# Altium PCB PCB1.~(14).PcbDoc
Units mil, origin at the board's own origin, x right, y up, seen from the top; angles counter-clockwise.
Board outline 2228.35 x 2228.35 mil, 2 copper layers (Top Layer, Bottom Layer); 36 components, 12 nets, 120 pads, 0 vias.
Unrouted connection lines stored in the file: 3.
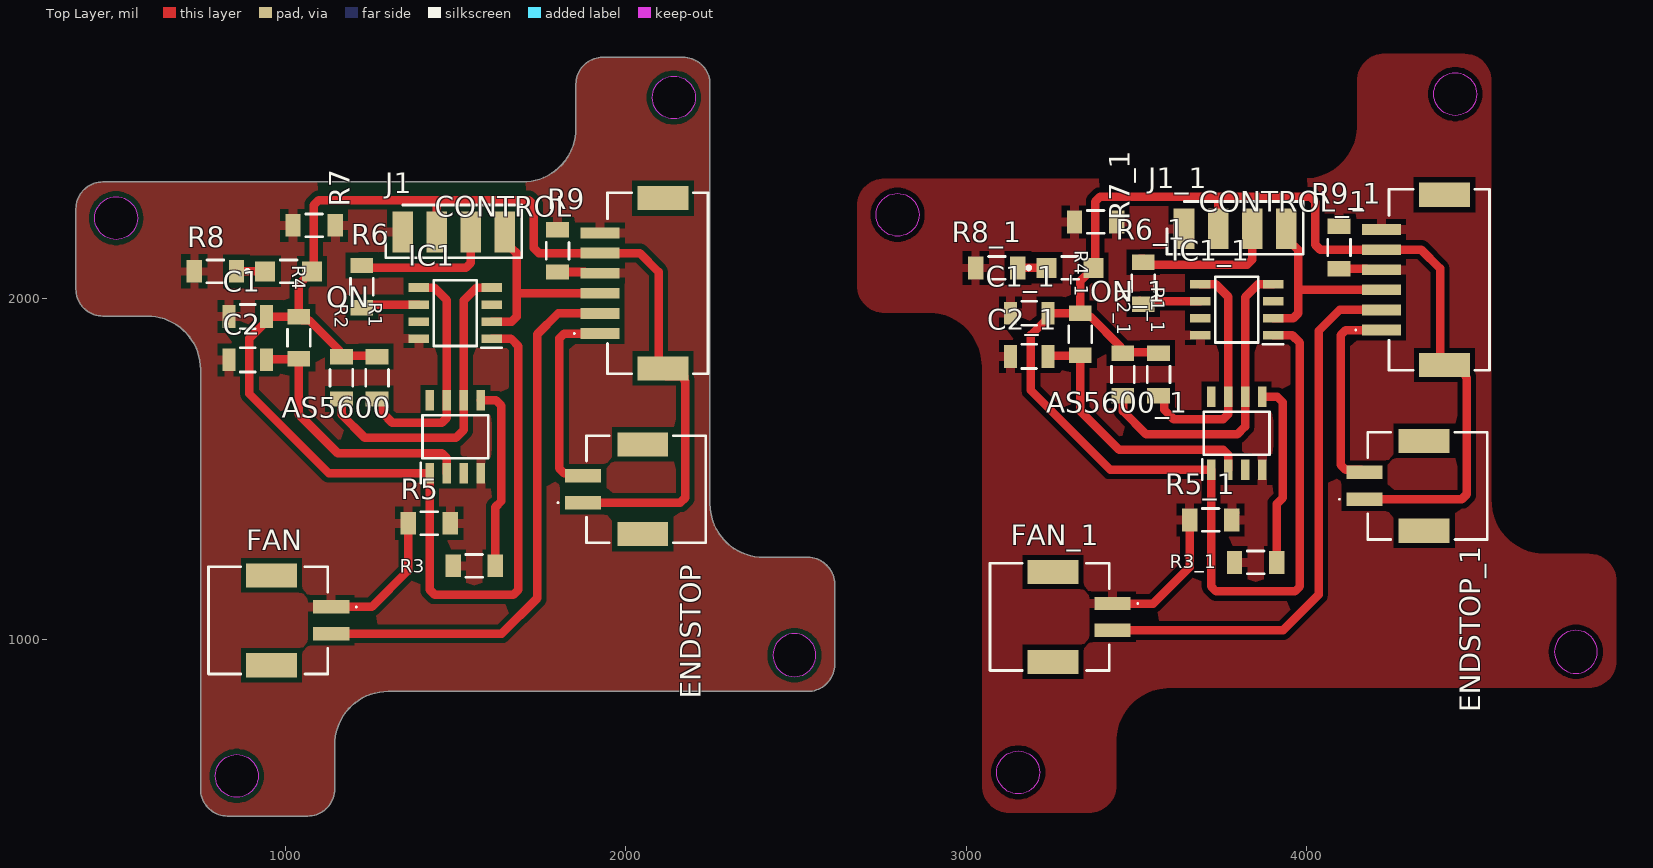
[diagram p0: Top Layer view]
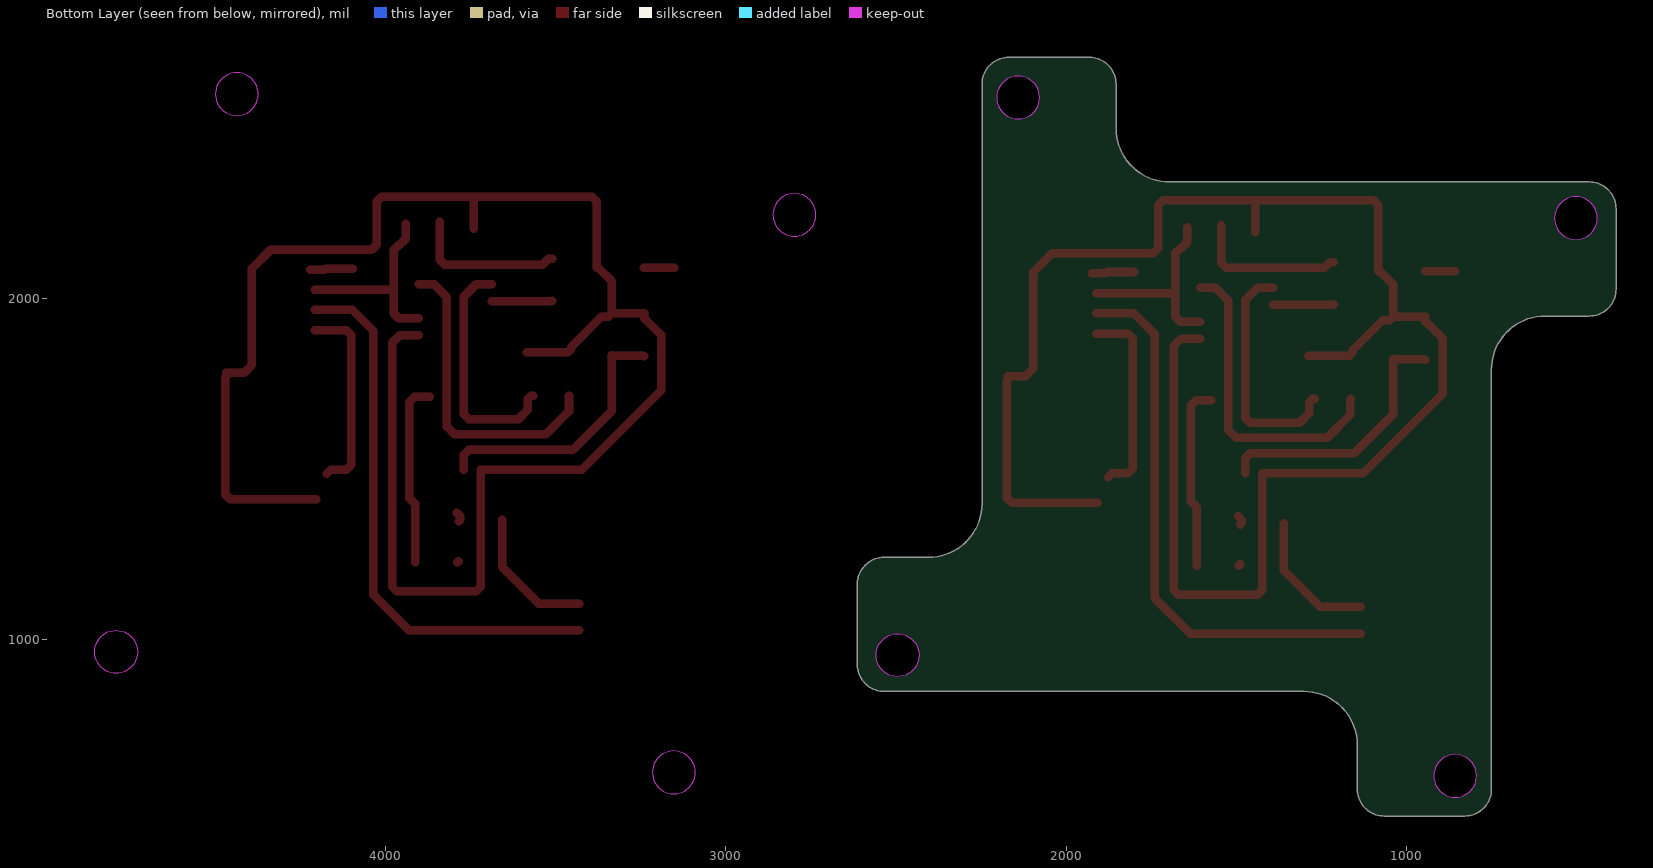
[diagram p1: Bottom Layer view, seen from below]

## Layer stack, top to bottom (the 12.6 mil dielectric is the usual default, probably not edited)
Top Solder: solder mask 0.4, Solder Resist, Dk 3.5
Top Layer: signal copper 1.4
Dielectric 1: dielectric 12.6, FR-4, Dk 4.8
Bottom Layer: signal copper 1.4
Bottom Solder: solder mask 0.4, Solder Resist, Dk 3.5

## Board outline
751.46,558.9 ccw(c830.2,558.9) 830.2,480.16 1066.42,480.16 ccw(c1066.42,558.9) 1145.16,558.9 1145.16,688.82 cw(c1302.64,688.82) 1302.64,846.3 2534.92,846.3 ccw(c2534.92,925.04) 2613.66,925.04 2613.66,1161.26 ccw(c2534.92,1161.26) 2534.92,1240 2405,1240 cw(c2405,1397.48) 2247.52,1397.48 2247.52,2629.76 ccw(c2168.78,2629.76) 2168.78,2708.5 1932.56,2708.5 ccw(c1932.56,2629.76) 1853.82,2629.76 1853.82,2499.84 cw(c1696.34,2499.84) 1696.34,2342.36 464.06,2342.36 ccw(c464.06,2263.62) 385.31,2263.62 385.31,2027.4 ccw(c464.06,2027.4) 464.06,1948.66 593.98,1948.66 cw(c593.98,1791.18) 751.46,1791.18
cut-out: 2798.43,2183.07 cw(c2798.43,2246.06) 2735.43,2246.06 cw(c2798.43,2246.06) 2798.43,2309.06 cw(c2798.43,2246.06) 2861.42,2246.06 cw(c2798.43,2246.06)
cut-out: 3089.76,608.27 cw(c3152.76,608.27) 3152.76,671.26 cw(c3152.76,608.27) 3215.75,608.27 cw(c3152.76,608.27) 3152.76,545.28 cw(c3152.76,608.27)
cut-out: 4436.22,2537.4 cw(c4436.22,2600.39) 4373.23,2600.39 cw(c4436.22,2600.39) 4436.22,2663.39 cw(c4436.22,2600.39) 4499.21,2600.39 cw(c4436.22,2600.39)
cut-out: 4727.56,962.6 ccw(c4790.55,962.6) 4790.55,899.61 ccw(c4790.55,962.6) 4853.54,962.6 ccw(c4790.55,962.6) 4790.55,1025.59 ccw(c4790.55,962.6)
cut-out: 2432.56,952.6 ccw(c2495.55,952.6) 2495.55,889.61 ccw(c2495.55,952.6) 2558.54,952.6 ccw(c2495.55,952.6) 2495.55,1015.59 ccw(c2495.55,952.6)
cut-out: 2141.22,2527.4 cw(c2141.22,2590.39) 2078.23,2590.39 cw(c2141.22,2590.39) 2141.22,2653.39 cw(c2141.22,2590.39) 2204.21,2590.39 cw(c2141.22,2590.39)
cut-out: 794.76,598.27 cw(c857.76,598.27) 857.76,661.26 cw(c857.76,598.27) 920.75,598.27 cw(c857.76,598.27) 857.76,535.28 cw(c857.76,598.27)
cut-out: 503.43,2173.07 cw(c503.43,2236.06) 440.43,2236.06 cw(c503.43,2236.06) 503.43,2299.06 cw(c503.43,2236.06) 566.42,2236.06 cw(c503.43,2236.06)

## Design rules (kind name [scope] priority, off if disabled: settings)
Clearance [All] p1: gap=15.75 ignorepadtopadclearanceinfootprint=FALSE
PlaneConnect [All] p1: planeconnectstyle=Relief reliefexpansion=20 reliefentries=4 reliefconductorwidth=30 reliefairgap=15.75
PolygonConnect [All] p1: connectstyle=Relief reliefconductorwidth=25 reliefentries=4 polygonreliefangle="90 Angle" conductorbypadedge=TRUE mindistance=15 enablemindistance=FALSE airgapwidth=16
RoutingVias [All] p1: holewidth=28 width=50 viastyle="Through Hole" minholewidth=28 minwidth=50 maxholewidth=28 maxwidth=50
SolderMaskExpansion [All] p1: expansion=4 istentingtop=FALSE
SupplyNets "Schematic Supply Nets_2" [InNet('+5')] p1: voltage=0.000
SupplyNets "Schematic Supply Nets_1" [InNet('+3.3')] p2: voltage=0.000
SupplyNets "Schematic Supply Nets" [InNet('GND')] p3: voltage=0.000
Width [All] p1: maxlimit=25 minlimit=25 preferedwidth=25
29 further rules are at their usual default settings.

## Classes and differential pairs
component class Sheet1: AS5600 C1 C2 CONTROL ENDSTOP FAN IC1 J1 ON R1 R2 R3 R4 R5 R6 R7 R8 R9

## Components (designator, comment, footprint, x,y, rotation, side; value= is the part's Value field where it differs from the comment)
AS5600 "AS5600-ASOM" SOIC127P600X175-8N 1499.49,1594.33 r90 top
AS5600_1 "AS5600-ASOM" SOIC127P600X175-8N 3794.49,1604.33 r90 top (schematic designator AS5600)
C1 "C1206C102K5HACAUTO" FP-C1206C-EB-MFG 890,1947.01 r180 top value="1,000 pF"
C1_1 "C1206C102K5HACAUTO" FP-C1206C-EB-MFG 3185,1957.01 r180 top value="1,000 pF" (schematic designator C1)
C2 "C1206C102K5HACAUTO" FP-C1206C-EB-MFG 890,1820 r180 top value="1,000 pF"
C2_1 "C1206C102K5HACAUTO" FP-C1206C-EB-MFG 3185,1830 r180 top value="1,000 pF" (schematic designator C2)
CONTROL "C" SM06BZESSTBLFSN 2083.43,2045 r270 top
CONTROL_1 "C" SM06BZESSTBLFSN 4378.43,2055 r270 top (schematic designator CONTROL)
ENDSTOP "SM02B-PASS-TBT__LF__SN_" SM02BPASSTBTLFSN 2055,1440 r270 top
ENDSTOP_1 "SM02B-PASS-TBT__LF__SN_" SM02BPASSTBTLFSN 4350,1450 r270 top (schematic designator ENDSTOP)
FAN "SM02B-PASS-TBT__LF__SN_" SM02BPASSTBTLFSN 955,1055 r90 top
FAN_1 "SM02B-PASS-TBT__LF__SN_" SM02BPASSTBTLFSN 3250,1065 r90 top (schematic designator FAN)
IC1 "ATTINY412-SSF" SOIC127P600X175-8N 1499.49,1957.23 r180 top
IC1_1 "ATTINY412-SSF" SOIC127P600X175-8N 3794.49,1967.23 r180 top (schematic designator IC1)
J1 "MTSW-104-07-G-S-000" HDRV4W64P0X254_1X4_1016X254X864P 1345,2195 r180 top
J1_1 "MTSW-104-07-G-S-000" HDRV4W64P0X254_1X4_1016X254X864P 3640,2205 r180 top (schematic designator J1)
ON "LTST-C150AKT" FP-LTST-C150AKT-MFG 1010,2080 r0 top
ON_1 "LTST-C150AKT" FP-LTST-C150AKT-MFG 3305,2090 r0 top (schematic designator ON)
R1 "CSR1206FT33L0" FP-CSR1206-MFG 1270,1767.01 r90 top
R1_1 "CSR1206FT33L0" FP-CSR1206-MFG 3565,1777.01 r90 top (schematic designator R1)
R2 "CSR1206FT33L0" FP-CSR1206-MFG 1165,1767.01 r90 top
R2_1 "CSR1206FT33L0" FP-CSR1206-MFG 3460,1777.01 r90 top (schematic designator R2)
R3 "CSR1206FT33L0" FP-CSR1206-MFG 1555,1215 r0 top
R3_1 "CSR1206FT33L0" FP-CSR1206-MFG 3850,1225 r0 top (schematic designator R3)
R4 "CSR1206FT33L0" FP-CSR1206-MFG 1040,1885 r270 top
R4_1 "CSR1206FT33L0" FP-CSR1206-MFG 3335,1895 r270 top (schematic designator R4)
R5 "CSR1206FT33L0" FP-CSR1206-MFG 1422.99,1340 r0 top
R5_1 "CSR1206FT33L0" FP-CSR1206-MFG 3717.99,1350 r0 top (schematic designator R5)
R6 "CSR1206FT33L0" FP-CSR1206-MFG 1225,2035 r90 top
R6_1 "CSR1206FT33L0" FP-CSR1206-MFG 3520,2045 r90 top (schematic designator R6)
R7 "CSR1206FT33L0" FP-CSR1206-MFG 1085,2215 r180 top
R7_1 "CSR1206FT33L0" FP-CSR1206-MFG 3380,2225 r180 top (schematic designator R7)
R8 "CSR1206FT33L0" FP-CSR1206-MFG 795,2080 r180 top
R8_1 "CSR1206FT33L0" FP-CSR1206-MFG 3090,2090 r180 top (schematic designator R8)
R9 "CSR1206FT33L0" FP-CSR1206-MFG 1800,2140 r90 top
R9_1 "CSR1206FT33L0" FP-CSR1206-MFG 4095,2150 r90 top (schematic designator R9)

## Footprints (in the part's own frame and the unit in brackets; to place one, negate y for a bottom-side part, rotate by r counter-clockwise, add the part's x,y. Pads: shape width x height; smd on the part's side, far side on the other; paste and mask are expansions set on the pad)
FP-C1206C-EB-MFG [mm]
  rect 0.95x1.7 smd paste+0 mask+0: 1(-1.4,0) 2(1.4,0)
  silkscreen extent -0.55,-0.9 0.55,0.9, body extent -2,-1 2,1, height 0.25
FP-CSR1206-MFG [mm]
  rect 1.15x1.7 smd paste+0 mask+0: 1(-1.575,0) 2(1.575,0)
  silkscreen extent -0.62,-0.85 0.62,0.85, body extent -2.25,-0.95 2.25,0.95, height 0.25
FP-LTST-C150AKT-MFG [mm]
  rect 1.5x1.5 smd paste+0 mask+0: 1(-1.75,0) 2(1.75,0)
  silkscreen extent -3.2,-0.85 0.62,0.85, body extent -2.6,-0.95 2.6,0.95, height 0.25
HDRV4W64P0X254_1X4_1016X254X864P [mil]
  rect 61.02x120 smd: 1(0,0) 2(-100,0) 3(-200,0) 4(-300,0)
  silkscreen extent -350,-80 50,75, body extent -350,-55 50,45, height 10
SM02BPASSTBTLFSN [mm]
  rect 1x2.7 smd: 1(1,-4.575) 2(-1,-4.575)
  rect 1.8x3.8 smd: 3(3.35,-0.125) 4(-3.35,-0.125)
  silkscreen extent -4,-6.5 4,4.57, body extent -4.07,-5.82 4.07,4.57, height 5.8
SM06BZESSTBLFSN [mm]
  rect 0.8x2.9 smd: 1(3.75,-4.025) 2(2.25,-4.025) 3(0.75,-4.025) 4(-0.75,-4.025) 5(-2.25,-4.025) 6(-3.75,-4.025)
  rect 1.8x3.8 smd: 7(6.35,0.675) 8(-6.35,0.675)
  silkscreen extent -6.75,-6 6.75,4.02, body extent -7.07,-5.4 7.07,4.03, height 5.9
SOIC127P600X175-8N [mm]
  rect 1.525x0.65 smd: 1(-2.712,1.905) 2(-2.712,0.635) 3(-2.712,-0.635) 4(-2.712,-1.905) 5(2.712,-1.905) 6(2.712,-0.635) 7(2.712,0.635) 8(2.712,1.905)
  silkscreen extent -3.47,-2.45 1.6,2.58, body extent -3,-2.45 3,2.45, height 1.75

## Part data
AS5600 AS5600_1: "Integrated Circuit", Manufacturer_Name="ams OSRAM", Mouser Part Number=985-AS5600-ASOM
C1 C1_1 C2 C2_1: library part CMP-03020-003638-1, "C1206 1,000 pF X8R 10.00% 50 V", Capacitance="1,000 pF", Manufacturer=KEMET, Package=C1206C-EB, Temperature="-55°C to +150°C", Temperature Characteristic=X8R, Temperature Coefficient=15%, Temperature Range High=+150°C, Temperature Range Low=-55°C, Tolerance=0.1, Voltage Rating="50 V"
CONTROL CONTROL_1: library part SM06B-ZESS-TB_LF__SN_, "Connector", Manufacturer_Name="JST (JAPAN SOLDERLESS TERMINALS)", Manufacturer_Part_Number=SM06B-ZESS-TB(LF)(SN)
ENDSTOP ENDSTOP_1 FAN FAN_1: "Connector", Arrow Part Number="SM02B-PASS-TBT (LF)(SN)", Manufacturer_Name="JST (JAPAN SOLDERLESS TERMINALS)"
IC1 IC1_1: "Integrated Circuit", Manufacturer_Name=Microchip, Mouser Part Number=579-ATTINY412-SSF
J1 J1_1: "Connector", Manufacturer_Name=SAMTEC
ON ON_1: library part CMP-22017-000004-1, "LED AMBER CLEAR SMD", Colour=Amber, Forward Current=30mA, Forward Voltage=2.1V, Manufacturer=Lite-On, Package=0, Power Dissipation=100mW, Reverse Voltage=5V, Temperature="-55°C to +85°C", Temperature Range High=+85°C, Temperature Range Low=-55°C
R1 R1_1 R2 R2_1 R3 R3_1 R4 R4_1 R5 R5_1 R6 R6_1 R7 R7_1 R8 R8_1 R9 R9_1: library part CMP-26527-002831-1, "General Purpose Thick Film Chip Resistor, 1206, 33mΩ, 1%, 0.5W", Case/Package=1206, Max Operating Temperature=155°C, Max Power Dissipation=500mW, Min Operating Temperature=-55°C, Package Quantity=5000, Resistance=33mR, Resistor Type="Thick Film", Temperature Coefficient=100ppm/°C, Tolerance=1%

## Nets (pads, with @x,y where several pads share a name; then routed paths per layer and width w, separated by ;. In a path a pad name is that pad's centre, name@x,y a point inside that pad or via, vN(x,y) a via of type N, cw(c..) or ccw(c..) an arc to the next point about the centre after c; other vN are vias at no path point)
+3.3: AS5600.2 C2.1 R4.2 | length 790.4
  Top Layer w25: C2.1 946.61,1821.5 1038.5,1821.5 R4.2 1040,1660 1154.17,1545.83 1459.55,1545.83 1474.19,1531.18 1474.19,1487.86 AS5600.2
+5: AS5600.1 C1.1 CONTROL.5 CONTROL.7 ENDSTOP.1 IC1.1 J1.2 ON.2 R1.2 R2.2 R4.1 | length 5309.5
  Top Layer w25: ON.2 1040,2041.1 R4.1 ; ON.2@1083.9,2080 1083.9,2274.61 1098.54,2289.25 1452.78,2289.25 ; R1.2@1290,1832.01 1169.17,1832.01 1159.04,1842.15 1159.04,1847.54 1069.7,1936.87 1050.14,1936.87 R4.1 ; J1.2 1445,2281.47 1452.78,2289.25 ; IC1.1 1662.77,1882.23 1685,1860 1685,1144.64 1670.36,1130 1439.13,1130 1424.49,1144.64 AS5600.1 1127.44,1487.56 895,1720 895,1883.37 937.68,1926.04 938.92,1926.04 945.12,1932.24 C1.1 R4.1 ; ENDSTOP.1@1908.3,1400.59 2160.36,1400.59 2175,1415.23 2175,1757.42 2172.3,1760.12 2172.3,1772.07 2119.51,1772.07 2096.57,1795 2096.57,2078.43 2041.42,2133.58 1911.54,2133.58 1744.64,2133.58 1730,2148.23 1730,2274.61 1715.36,2289.25 1452.78,2289.25
END: CONTROL.1 ENDSTOP.2 | length 577.4
  Top Layer w25: ENDSTOP.2@1877.39,1475 1865.84,1486.56 1819.64,1486.56 1805,1501.2 1805,1882.72 1819.64,1897.36 CONTROL.1@1911.54,1897.36
FAN: CONTROL.2 FAN.2 | length 1620.1
  Top Layer w25: FAN.2 1635.63,1015.63 1740,1120 1740,1895 1801.42,1956.42 CONTROL.2@1911.54,1956.42
GND: AS5600.4 C1.2 C2.2 CONTROL.4 CONTROL.6 FAN.1 IC1.8 J1.1 R3.1 R5.1 R5.2 R7.1 R7.2 R8.2 R9.1 R9.2 | length 567.5
  Top Layer w25: FAN.1 1254.37,1094.37 1360.98,1200.98 R5.1 ; R5.2 R5.2@1489,1336 ; R5.2@1485,1344.43 1485,1350.83 R5.2@1495.14,1360.96 ; R3.1@1489,1219 R3.1 ; R9.1 1880.16,2077.99 1883.62,2074.53 CONTROL.4
NetAS5600_5: AS5600.5 R3.2 | length 544.6
  Top Layer w25: AS5600.5 1618.9,1701.1 1635,1685 1635,1405 1617.01,1387.01 R3.2
NetIC1_6: IC1.6 R6.1 | length 178
  Top Layer w25: R6.1@1215,1982.99 1215.76,1982.23 IC1.6
NetON_1: ON.1 R8.1 | length 89.1
  Top Layer w25: R8.1 ON.1@946.1,2080
SCL: AS5600.7 IC1.5 R1.1 | length 700.3
  Top Layer w25: R1.1 1276.93,1705 1287.07,1694.86 1287.07,1662.93 1314.57,1635.43 1459.55,1635.43 1474.19,1650.07 1474.19,1700.81 AS5600.7 1474.49,1995.51 1438.07,2031.93 1393.01,2031.93 IC1.5
SDA: AS5600.6 IC1.4 R2.1 | length 920
  Top Layer w25: R2.1 1165.49,1704.51 1165.49,1659.51 1233.79,1591.21 1501.21,1591.21 1524.19,1614.19 1524.19,1700.81 AS5600.6 1524.49,1994.49 1561.93,2031.93 1605.96,2031.93 IC1.4
TX: CONTROL.3 IC1.2 J1.4 | length 590
  Top Layer w25: IC1.2 1665.36,1932.23 1680,1946.87 1680,2015.47 ; J1.4@1645,2209.64 1645,2165.51 1663.01,2147.5 1665.36,2147.5 1680,2132.86 1680,2015.47 ; CONTROL.3@1911.54,2015.47 1680,2015.47
UPDI: J1.3 R6.2 | length 453.5
  Top Layer w25: R6.2@1215,2107.01 1225.83,2107.01 1242.83,2090 1530.36,2090 1545,2104.64 J1.3@1545,2215
pads on no net: AS5600.3 AS5600.8 AS5600_1.1 AS5600_1.2 AS5600_1.3 AS5600_1.4 AS5600_1.5 AS5600_1.6 AS5600_1.7 AS5600_1.8 C1_1.1 C1_1.2 C2_1.1 C2_1.2 CONTROL.8 CONTROL_1.1 CONTROL_1.2 CONTROL_1.3 CONTROL_1.4 CONTROL_1.5 CONTROL_1.6 CONTROL_1.7 CONTROL_1.8 ENDSTOP.3 ENDSTOP.4 ENDSTOP_1.1 ENDSTOP_1.2 ENDSTOP_1.3 ENDSTOP_1.4 FAN.3 FAN.4 FAN_1.1 FAN_1.2 FAN_1.3 FAN_1.4 IC1.3 IC1.7 IC1_1.1 IC1_1.2 IC1_1.3 IC1_1.4 IC1_1.5 IC1_1.6 IC1_1.7 IC1_1.8 J1_1.1 J1_1.2 J1_1.3 J1_1.4 ON_1.1 ON_1.2 R1_1.1 R1_1.2 R2_1.1 R2_1.2 R3_1.1 R3_1.2 R4_1.1 R4_1.2 R5_1.1 R5_1.2 R6_1.1 R6_1.2 R7_1.1 R7_1.2 R8_1.1 R8_1.2 R9_1.1 R9_1.2
copper on no net: | length 12340.4
  Top Layer w25: 3152.01,2090 3241.1,2090 ; 3240.12,1830 3241.61,1831.5 3333.5,1831.5 3335,1832.99 3335,1670 3449.17,1555.83 3754.55,1555.83 3769.19,1541.18 3769.19,1497.86 3769.49,1497.56 ; 3373.9,2090 3335,2051.1 3335,1957.01 ; 3378.9,2090 3378.9,2284.61 3393.54,2299.25 3747.78,2299.25 ; 3430.12,1025.63 3930.63,1025.63 4035,1130 4035,1905 4096.42,1966.42 4206.54,1966.42 ; 3430.12,1104.37 3549.37,1104.37 3655.98,1210.98 3655.98,1350 ; 3460,1715 3460.49,1714.51 3460.49,1669.51 3528.79,1601.21 3796.21,1601.21 3819.19,1624.19 3819.19,1710.81 3819.49,1711.1 3819.49,2004.49 3856.93,2041.93 3900.96,2041.93 3901.26,2042.23 ; 3510,1992.99 3510.76,1992.23 3687.72,1992.23 ; 3510,2117.01 3520.83,2117.01 3537.83,2100 3825.36,2100 3840,2114.64 3840,2225 ; 3565,1715 3571.93,1715 3582.07,1704.86 3582.07,1672.93 3609.57,1645.43 3754.55,1645.43 3769.19,1660.07 3769.19,1710.81 3769.49,1711.1 3769.49,2005.51 3733.07,2041.93 3688.01,2041.93 3687.72,2042.23 ; 3585,1842.01 3464.17,1842.01 3454.04,1852.15 3454.04,1857.54 3364.7,1946.87 3345.14,1946.87 3335,1957.01 ; 3740,2205 3740,2291.47 3747.78,2299.25 ; 3780,1350 3784,1346 ; 3780,1354.43 3780,1360.83 3790.14,1370.96 ; 3784,1229 3787.99,1225 ; 3869.49,1711.1 3913.9,1711.1 3930,1695 3930,1415 3912.01,1397.01 3912.01,1225 ; 3901.26,1892.23 3957.77,1892.23 3980,1870 3980,1154.64 3965.36,1140 3734.13,1140 3719.49,1154.64 3719.49,1497.56 3422.44,1497.56 3190,1730 3190,1893.37 3232.68,1936.04 3233.92,1936.04 3240.12,1942.24 3240.12,1957.01 3335,1957.01 ; 3901.26,1942.23 3960.36,1942.23 3975,1956.87 3975,2025.47 ; 3940,2219.64 3940,2175.51 3958.01,2157.5 3960.36,2157.5 3975,2142.86 3975,2025.47 ; 4095,2087.99 4175.16,2087.99 4178.62,2084.53 4219.96,2084.53 ; 4172.39,1485 4160.84,1496.56 4114.64,1496.56 4100,1511.2 4100,1892.72 4114.64,1907.36 4206.54,1907.36 ; 4203.3,1410.59 4455.36,1410.59 4470,1425.23 4470,1767.42 4467.3,1770.12 4467.3,1782.07 4414.51,1782.07 4391.57,1805 4391.57,2088.43 4336.42,2143.58 4206.54,2143.58 4039.64,2143.58 4025,2158.23 4025,2284.61 4010.36,2299.25 3747.78,2299.25 ; 4206.54,2025.47 3975,2025.47

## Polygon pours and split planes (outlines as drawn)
no net on Top Layer "NONET_L01_P007" (solid, pour order 7): 3125.2,490.16 3361.42,490.16 ccw(c3361.42,568.9) 3440.16,568.9 3440.16,698.82 cw(c3597.64,698.82) 3597.64,856.3 4829.92,856.3 ccw(c4829.92,935.04) 4908.66,935.04 4908.66,1171.26 ccw(c4829.92,1171.26) 4829.92,1250 4700,1250 cw(c4700,1407.48) 4542.52,1407.48 4542.52,2639.76 ccw(c4463.78,2639.76) 4463.78,2718.5 4227.56,2718.5 ccw(c4227.56,2639.76) 4148.82,2639.76 4148.82,2509.84 cw(c3991.34,2509.84) 3991.34,2352.36 2759.06,2352.36 ccw(c2759.06,2273.62) 2680.31,2273.62 2680.32,2037.4 ccw(c2759.06,2037.4) 2759.06,1958.66 2888.98,1958.66 cw(c2888.98,1801.18) 3046.46,1801.18 3046.46,568.9 ccw(c3125.2,568.9)
GND on Top Layer "GND_L01_P000" (solid, pour order 0): 830.2,480.16 1066.42,480.16 ccw(c1066.42,558.9) 1145.16,558.9 1145.16,688.82 cw(c1302.64,688.82) 1302.64,846.3 2534.92,846.3 ccw(c2534.92,925.04) 2613.66,925.04 2613.66,1161.26 ccw(c2534.92,1161.26) 2534.92,1240 2405,1240 cw(c2405,1397.48) 2247.52,1397.48 2247.52,2629.76 ccw(c2168.78,2629.76) 2168.78,2708.5 1932.56,2708.5 ccw(c1932.56,2629.76) 1853.82,2629.76 1853.82,2499.84 cw(c1696.34,2499.84) 1696.34,2342.36 464.06,2342.36 ccw(c464.06,2263.62) 385.31,2263.62 385.32,2027.4 ccw(c464.06,2027.4) 464.06,1948.66 593.98,1948.66 cw(c593.98,1791.18) 751.46,1791.18 751.46,558.9 ccw(c830.2,558.9)

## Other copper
Bottom Layer:
  rectangle: 175,5370 6080.51,9307.01

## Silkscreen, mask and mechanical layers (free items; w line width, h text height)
Mechanical 1:
  circle w0.5: c4436.22,2600.39 r62.99
  circle w0.5: c3152.76,608.27 r62.99
  circle w0.5: c2798.43,2246.06 r62.99
  circle w1: c4790.55,962.6 r62.99
  circle w1: c2495.55,952.6 r62.99
  circle w0.5: c503.43,2236.06 r62.99
  circle w0.5: c857.76,598.27 r62.99
  circle w0.5: c2141.22,2590.39 r62.99
  lines w0.5: 385.31,2027.4 ccw(c464.06,2027.4) 464.06,1948.66 593.98,1948.66 cw(c593.98,1791.18) 751.46,1791.18 751.46,558.9 ccw(c830.2,558.9) 830.2,480.16 1066.42,480.16 ccw(c1066.42,558.9) 1145.16,558.9 1145.16,688.82 cw(c1302.64,688.82) 1302.64,846.3 2534.92,846.3 ccw(c2534.92,925.04) 2613.66,925.04 2613.66,1161.26 ccw(c2534.92,1161.26) 2534.92,1240 2405,1240 cw(c2405,1397.48) 2247.52,1397.48 2247.52,2629.76 ccw(c2168.78,2629.76) 2168.78,2708.5 1932.56,2708.5 ccw(c1932.56,2629.76) 1853.82,2629.76 1853.82,2499.84 cw(c1696.34,2499.84) 1696.34,2342.36 464.06,2342.36 ccw(c464.06,2263.62) 385.31,2263.62 385.32,2027.4 ; 2680.31,2037.4 ccw(c2759.06,2037.4) 2759.06,1958.66 2888.98,1958.66 cw(c2888.98,1801.18) 3046.46,1801.18 3046.46,568.9 ccw(c3125.2,568.9) 3125.2,490.16 3361.42,490.16 ccw(c3361.42,568.9) 3440.16,568.9 3440.16,698.82 cw(c3597.64,698.82) 3597.64,856.3 4829.92,856.3 ccw(c4829.92,935.04) 4908.66,935.04 4908.66,1171.26 ccw(c4829.92,1171.26) 4829.92,1250 4700,1250 cw(c4700,1407.48) 4542.52,1407.48 4542.52,2639.76 ccw(c4463.78,2639.76) 4463.78,2718.5 4227.56,2718.5 ccw(c4227.56,2639.76) 4148.82,2639.76 4148.82,2509.84 cw(c3991.34,2509.84) 3991.34,2352.36 2759.06,2352.36 ccw(c2759.06,2273.62) 2680.31,2273.62 2680.32,2037.4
